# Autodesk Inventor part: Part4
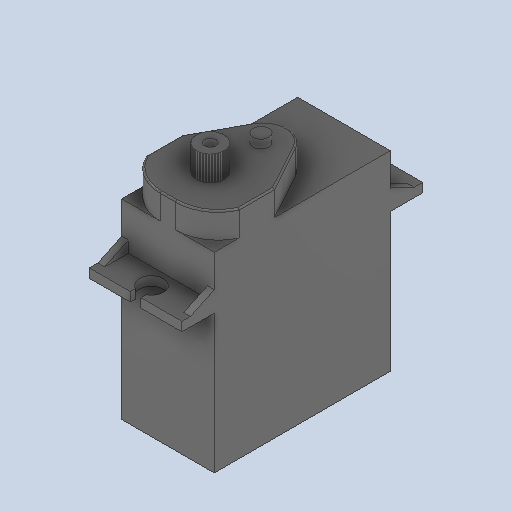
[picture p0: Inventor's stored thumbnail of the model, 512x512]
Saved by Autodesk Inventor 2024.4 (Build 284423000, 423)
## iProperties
Created: 2025-06
Part Number: Part4
Material: Generic
Document SubType Name: Modeling
Designer: AdminForWorker
Density: 1 g/cm^3
Appearance: Default
Author: AdminForWorker
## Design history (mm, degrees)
feature "Body1"
body "Solid1"
